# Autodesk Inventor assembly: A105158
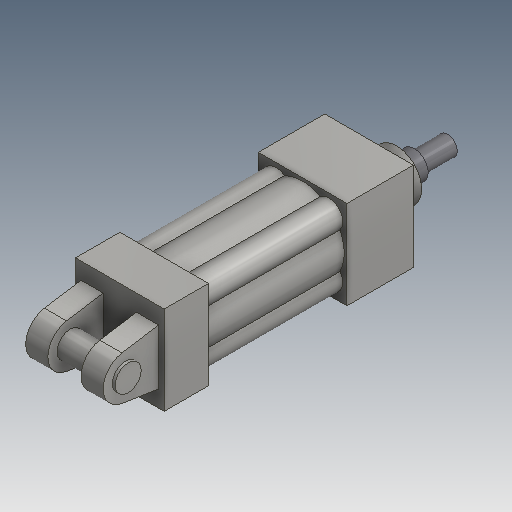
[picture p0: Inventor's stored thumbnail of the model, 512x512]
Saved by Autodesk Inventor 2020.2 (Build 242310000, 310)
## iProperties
Created: 2000-02
Part Number: A105158
Description: CYL,CLEV
Document SubType Name: Assembly
Designer: sspink
Mass: 567.314 g
Surface Area: 672.21 cm^2
Volume: 183.139 cm^3
Density: 3.09773 g/cm^3
Control State: 0
Checked Out: False
Master: False
Shininess: 0.0
Length Units: 11272
Angle Units: 11279
Time Units: 11290
Mass Units: 11286
Length Display Precision: 3
Angle Display Precision: 2
Compacted: True
Dimensions: 2x8,6x2 in
Mass: 1,251 lb
DocNumber: A105158.iam
Folder: 01 - Themengebiete\Simplification\01 - Packaging machine\
VDS_Category: 3D Komponenten
Density: 0.0
Volumn: 0.0
Area: 0.0
PropertySet Name: Model Information
Author: sspink
Revision Number: -
Title: Zylinder
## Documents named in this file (3)
- D:\07 - DEMODATEN\OTX 2019 - Dataset - UPDATE - Dez2019\Designs\07-Packing machine\A105158.iam
- D:\07 - DEMODATEN\OTX 2019 - Dataset - UPDATE - Dez2019\Designs\07-Packing machine\Parts\ADSK-011794.ipt
- D:\07 - DEMODATEN\OTX 2019 - Dataset - UPDATE - Dez2019\Designs\07-Packing machine\Parts\ADSK-011795.ipt
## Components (2 placed, 2 different names)
1. ADSK-011794:1 — Mate:1, Mate:2, Mate:3, Einfügen:1
2. ADSK-011795:1 — Einfügen:1
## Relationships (4: Mate 3, Insert 1)
- Mate:1: ADSK-011794:1
- Mate:2: ADSK-011794:1
- Mate:3: ADSK-011794:1
- Einfügen:1 [Insert]: ADSK-011794:1 ↔ ADSK-011795:1
